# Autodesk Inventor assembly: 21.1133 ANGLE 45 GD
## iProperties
Created: 2007-01
Part Number: 21.1133 ANGLE 45 GD
Document SubType Name: Assembly
Designer: Andy Moles
Mass: 116.196 g
Surface Area: 146.089 cm^2
Volume: 33.7492 cm^3
Density: 3.44294 g/cm^3
Author: Andy Moles
